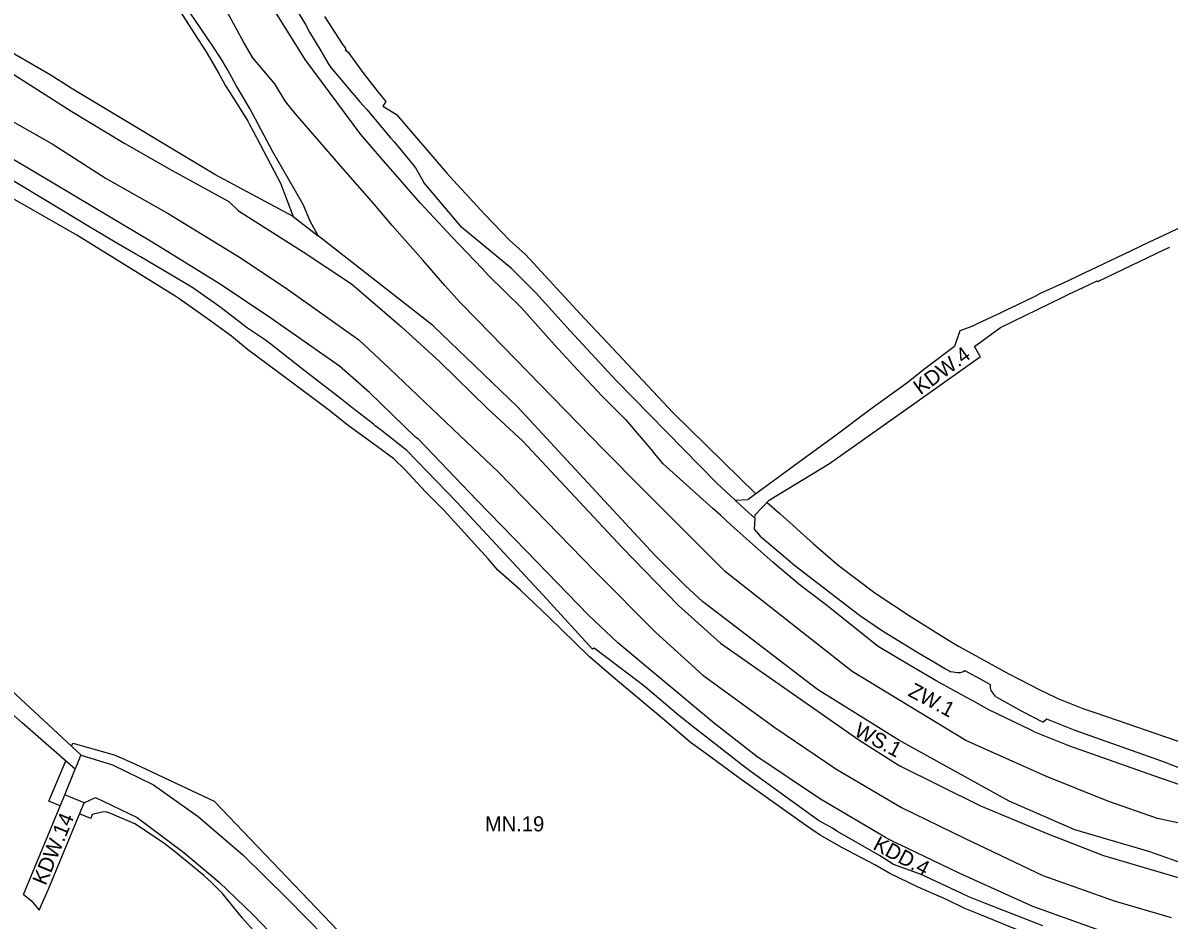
# Model space of a CAD drawing. Extents: x 7418991 to 7423142, y 5547704 to 5549547.
# Drawn here: x 7419654.4 to 7420035, y 5548518.9 to 5548816.8 of the extents above; entities that cross this region are included whole.
import ezdxf

# ---------------------------------------------------------------- set-up
doc = ezdxf.new("R2010")
doc.units = 0
for name, color, linetype in [('LIN_Linia Zabudowy Nieprzekraczalna', 7, 'Continuous'), ('LIN_linie_rozgraniczajace', 7, 'Continuous'), ('TXT_Oznaczenia_przeznaczen', 7, 'Continuous')]:
    doc.layers.add(name, color=color, linetype=linetype)

msp = doc.modelspace()

# ---------------------------------------------------------------- linework, layer by layer
at = {"layer": 'LIN_Linia Zabudowy Nieprzekraczalna'}
for p, q in [((7419937.32, 5548627.58), (7419949.3, 5548619.59)), ((7419691.76, 5548570.62), (7419717.86, 5548558.33)), ((7419666.76, 5548556.84), (7419663.06, 5548558.36)), ((7419717.86, 5548558.33), (7419819.96, 5548451.81))]:
    msp.add_line(p, q, dxfattribs=at)
for points in [[(7419754.53, 5548818.94), (7419759.18, 5548811.75), (7419760.41, 5548809.86), (7419761.61, 5548808.2), (7419761.39, 5548807.85), (7419762.33, 5548807.21), (7419767.57, 5548799.96), (7419772.34, 5548793.88), (7419774.86, 5548790.72), (7419773.92, 5548789.24), (7419778.4, 5548786.37), (7419795.11, 5548766.94), (7419796.13, 5548765.86), (7419806.44, 5548754.65), (7419807.78, 5548753.26), (7419816.01, 5548744.72), (7419821.27, 5548739.89), (7419840.89, 5548718.65), (7419846.84, 5548712.32), (7419870.33, 5548687.32), (7419897.75, 5548660.43)], [(7419986.71, 5548514.81), (7419972.13, 5548520.75), (7419967.13, 5548522.75), (7419961.25, 5548525.56), (7419951.7, 5548529.86), (7419942.26, 5548534.33), (7419937.31, 5548537.26), (7419926.3, 5548542.97), (7419919.08, 5548547.12), (7419914.29, 5548550.42), (7419892.49, 5548565.85), (7419881.13, 5548574.18), (7419876.11, 5548577.89), (7419868.06, 5548584.71), (7419868.09, 5548584.68), (7419851.11, 5548598.84), (7419842.52, 5548606.35), (7419837.65, 5548611.12), (7419829.01, 5548619.47), (7419819.47, 5548628.55), (7419812.05, 5548635.09), (7419808.83, 5548638.85), (7419794.23, 5548654.87), (7419788.11, 5548661.14), (7419783.95, 5548665.51), (7419781.38, 5548668.37), (7419777.69, 5548671.99), (7419777.58, 5548672.08), (7419772.17, 5548676.08), (7419766.82, 5548679.97), (7419762.37, 5548683.12), (7419757.56, 5548686.96), (7419756.3, 5548687.99), (7419751.87, 5548691.33), (7419739.32, 5548700.74), (7419729.02, 5548708.43), (7419723.61, 5548712.8), (7419715.97, 5548718.38), (7419706.15, 5548725.28), (7419705.21, 5548726.01), (7419672.29, 5548746.33), (7419651.66, 5548758.24)], [(7419901.48, 5548657.59), (7419905.76, 5548653.92), (7419916.9, 5548643.82), (7419925.15, 5548636.77), (7419937.32, 5548627.58)], [(7419949.3, 5548619.59), (7419956.38, 5548615.21), (7419961.76, 5548611.89), (7419965.11, 5548609.9), (7419981.5, 5548600.8)], [(7419981.5, 5548600.8), (7419992.1, 5548595.34), (7419997.1, 5548592.94), (7419998.04, 5548592.5), (7420006.38, 5548589.15), (7420010.64, 5548587.74), (7420040.89, 5548577.34), (7420048.53, 5548574.46), (7420054.4, 5548572.62), (7420067.89, 5548569.27), (7420082.96, 5548566.23), (7420086.13, 5548563.32), (7420087.87, 5548565.39), (7420099.95, 5548563.83)], [(7419670.56, 5548576.59), (7419670.98, 5548577.59)], [(7419670.98, 5548577.59), (7419684.69, 5548573.79), (7419686.98, 5548572.8), (7419691.76, 5548570.62)], [(7419663.06, 5548558.36), (7419668.6, 5548571.82)], [(7419744.03, 5548500.72), (7419727.35, 5548519.57), (7419720.7, 5548527.73), (7419717.06, 5548531.35), (7419714.5, 5548533.71), (7419708.88, 5548538.35), (7419704.11, 5548542.21), (7419700.7, 5548544.76), (7419691.58, 5548550.83), (7419683.24, 5548554.35), (7419682.25, 5548554.73), (7419681.66, 5548554.86), (7419680.74, 5548554.67), (7419677.44, 5548553.91), (7419676.93, 5548552.65), (7419673.23, 5548554.17)]]:
    msp.add_lwpolyline(points, dxfattribs=at)
at = {"layer": 'LIN_linie_rozgraniczajace'}
for p, q in [((7419727.78, 5548810.3), (7419722.21, 5548820.53)), ((7419730.71, 5548805.22), (7419727.78, 5548810.3)), ((7419738.01, 5548796.65), (7419730.71, 5548805.22)), ((7419629.93, 5548795.98), (7419664.13, 5548776.68)), ((7419741.56, 5548790.77), (7419738.01, 5548796.65)), ((7419744.88, 5548786.66), (7419741.56, 5548790.77)), ((7419760.78, 5548768.35), (7419744.88, 5548786.66)), ((7419664.13, 5548776.68), (7419682.01, 5548765.19)), ((7419770.98, 5548756.66), (7419760.78, 5548768.35)), ((7419784.81, 5548768.75), (7419787.49, 5548763.79)), ((7419682.01, 5548765.19), (7419702.58, 5548753.57)), ((7419777.06, 5548749.55), (7419770.98, 5548756.66)), ((7419702.58, 5548753.57), (7419726.89, 5548738.7)), ((7419744.14, 5548752.54), (7419752.39, 5548746.16)), ((7419787.26, 5548737.92), (7419777.06, 5548749.55)), ((7419726.89, 5548738.7), (7419742.2, 5548728.4)), ((7419794.52, 5548729.6), (7419787.26, 5548737.92)), ((7419824.87, 5548727.13), (7419816.59, 5548735.31)), ((7419819.8, 5548722.3), (7419809.09, 5548732.89)), ((7419742.2, 5548728.4), (7419765.96, 5548711.61)), ((7419799.48, 5548724.12), (7419794.52, 5548729.6)), ((7419805.23, 5548718.21), (7419799.48, 5548724.12)), ((7419734.93, 5548711.49), (7419728.96, 5548715.51)), ((7419847.2, 5548675.17), (7419805.23, 5548718.21)), ((7419765.96, 5548711.61), (7419776.19, 5548701.96)), ((7419776.19, 5548701.96), (7419799.52, 5548679.82)), ((7419884.76, 5548664.03), (7419851.55, 5548698)), ((7419854.5, 5548685.15), (7419863.51, 5548674.45)), ((7419799.52, 5548679.82), (7419812.24, 5548667.78)), ((7419860.22, 5548661.95), (7419847.2, 5548675.17)), ((7419812.24, 5548667.78), (7419844.34, 5548634.78)), ((7419869.72, 5548652.42), (7419860.22, 5548661.95)), ((7419890.92, 5548658.32), (7419895.25, 5548658.6)), ((7419877.85, 5548644.36), (7419869.72, 5548652.42)), ((7419897.47, 5548652.39), (7419897.54, 5548653.52)), ((7419887.7, 5548634.51), (7419877.85, 5548644.36)), ((7419844.34, 5548634.78), (7419864.56, 5548614.41)), ((7419929.74, 5548601.42), (7419887.7, 5548634.51)), ((7419851.92, 5548610.94), (7419842.08, 5548620.22)), ((7419864.56, 5548614.41), (7419880.15, 5548600.19)), ((7419884.02, 5548584.12), (7419851.92, 5548610.94)), ((7419967.48, 5548578.48), (7419929.74, 5548601.42)), ((7419880.15, 5548600.19), (7419904.1, 5548582.84)), ((7419994.36, 5548585.58), (7419993.22, 5548584.61)), ((7419904.1, 5548582.84), (7419924.32, 5548569.12)), ((7419994.3, 5548566.54), (7419967.48, 5548578.48)), ((7419924.32, 5548569.12), (7419946.14, 5548556.24)), ((7420014.64, 5548558.32), (7419994.3, 5548566.54)), ((7419674.75, 5548557.87), (7419668.28, 5548560.53)), ((7419946.14, 5548556.24), (7419967.03, 5548546.06)), ((7420031.14, 5548552.63), (7420014.64, 5548558.32)), ((7420048.85, 5548548.76), (7420031.14, 5548552.63)), ((7419940.8, 5548546.35), (7419945.27, 5548544.1)), ((7419967.03, 5548546.06), (7419993.09, 5548533.7)), ((7419993.09, 5548533.7), (7420016.69, 5548525.28)), ((7420016.69, 5548525.28), (7420035.64, 5548519.71))]:
    msp.add_line(p, q, dxfattribs=at)
for points in [[(7419725.26, 5548796.05), (7419722.48, 5548801.11), (7419720.88, 5548803.83), (7419720.03, 5548805.19), (7419717.65, 5548808.74), (7419713.44, 5548815.02), (7419708.31, 5548822.59), (7419706.01, 5548826.24), (7419702.41, 5548832.08), (7419698.25, 5548838.79), (7419694.79, 5548844.36), (7419690.11, 5548854.93), (7419687.2, 5548861.42), (7419682.37, 5548869.22), (7419679.61, 5548873.71), (7419676.54, 5548879.52), (7419674.86, 5548882.62)], [(7419717.15, 5548869.39), (7419723.59, 5548857.61), (7419729.07, 5548847.98), (7419748.22, 5548816.34), (7419749.51, 5548813.77), (7419753.32, 5548807.54), (7419755.8, 5548803.39), (7419756.6, 5548802), (7419763.76, 5548793.63), (7419766.31, 5548790.65), (7419768.6, 5548788.05), (7419776.43, 5548778.71), (7419777.63, 5548777.29), (7419780.05, 5548774.53), (7419784.81, 5548768.75)], [(7419681.66, 5548865.01), (7419686.39, 5548855.19), (7419695.39, 5548836.11), (7419700.86, 5548829.76), (7419707.66, 5548819.11), (7419711.37, 5548813.25), (7419715.25, 5548807.22), (7419719.45, 5548799.99), (7419721.69, 5548795.94)], [(7419773.52, 5548771.86), (7419766.66, 5548779.77), (7419748.11, 5548804.68), (7419735.05, 5548825.68), (7419723.7, 5548844.72)], [(7419672.39, 5548793.99), (7419670.45, 5548795.12), (7419663.47, 5548799.57), (7419645.7, 5548809.82), (7419626.86, 5548821.22), (7419612.15, 5548830.31), (7419604.5, 5548834.35), (7419599.55, 5548837.33), (7419592.42, 5548841.53), (7419590.61, 5548842.54)], [(7419625.5, 5548814.25), (7419646.9, 5548802.53), (7419670.62, 5548787.47), (7419688.23, 5548776.78), (7419703.95, 5548767.79), (7419722.74, 5548757.55), (7419726.03, 5548754.45), (7419747.43, 5548740.85), (7419763.5, 5548730.15), (7419780.13, 5548715.88), (7419792.86, 5548704.27), (7419808.71, 5548688.73), (7419820.43, 5548677.88), (7419853.39, 5548642.59), (7419872.11, 5548623.4), (7419886.03, 5548610.8), (7419931.98, 5548578.77), (7419945.38, 5548570.24), (7419972.32, 5548556.78), (7419994.74, 5548547.57), (7420013.19, 5548540.38), (7420039.08, 5548532.71)], [(7419721.69, 5548795.94), (7419723.07, 5548793.77), (7419724.4, 5548791.65), (7419725.74, 5548789.54), (7419727.08, 5548787.4), (7419728.41, 5548785.29), (7419729.11, 5548784.19), (7419729.67, 5548783.13), (7419730.85, 5548780.92), (7419735.5, 5548772.05), (7419739.88, 5548763.61), (7419744.14, 5548752.54), (7419718.18, 5548766.44), (7419672.39, 5548793.99)], [(7419880.08, 5548624.72), (7419874.36, 5548629.84), (7419864.28, 5548640.06), (7419837.73, 5548668.58), (7419818.59, 5548689.36), (7419790.53, 5548716.39), (7419752.39, 5548746.16), (7419749.83, 5548751.02), (7419747.43, 5548756.52), (7419742.36, 5548765.35), (7419737.4, 5548774.06), (7419729.71, 5548788.36), (7419725.26, 5548796.05)], [(7419784.8, 5548679.24), (7419769.44, 5548694.15), (7419759.49, 5548702.88), (7419736.73, 5548718.74), (7419720.21, 5548729.84), (7419697.28, 5548744.04), (7419677.6, 5548755.76), (7419657.58, 5548767.66), (7419640.53, 5548777.71)], [(7419809.09, 5548732.89), (7419806.87, 5548735.33), (7419796.98, 5548745.67), (7419786.34, 5548757.03), (7419783.16, 5548760.68), (7419780.37, 5548763.94), (7419773.52, 5548771.86)], [(7419728.96, 5548715.51), (7419720.27, 5548722.23), (7419717.94, 5548723.83), (7419710.46, 5548729.13), (7419693.47, 5548739.11), (7419691.92, 5548740.02), (7419685.6, 5548743.73), (7419677.45, 5548748.53), (7419666.76, 5548755), (7419647.49, 5548766.65)], [(7419816.59, 5548735.31), (7419800.13, 5548748.9), (7419787.49, 5548763.79)], [(7420048.98, 5548753.84), (7420034.77, 5548747.05), (7420028.32, 5548744.02), (7420022.17, 5548741.05), (7420006.82, 5548733.72), (7419999.56, 5548730.35), (7419992.15, 5548726.93), (7419990.41, 5548726), (7419984.39, 5548723.1), (7419981.06, 5548721.51), (7419978.65, 5548720.29), (7419971.69, 5548717.07), (7419969.52, 5548716.05), (7419965.54, 5548714.54), (7419963.78, 5548709.33), (7419953.83, 5548701.96), (7419947.9, 5548697.2), (7419935.64, 5548688.32), (7419924.39, 5548679.89), (7419911.81, 5548670.7), (7419895.25, 5548658.6)], [(7419972.12, 5548706.25), (7419970.32, 5548709.33), (7419979.01, 5548715.71), (7419999.49, 5548725.68), (7420000.55, 5548726.2), (7420001.72, 5548726.73), (7420006.42, 5548728.93), (7420011.14, 5548731.21), (7420011.28, 5548730.99), (7420033.45, 5548741.57), (7420035.26, 5548742.34)], [(7419824.87, 5548727.13), (7419836.08, 5548714.63), (7419851.55, 5548698)], [(7419854.5, 5548685.15), (7419850.5, 5548689.15), (7419846.51, 5548693.14), (7419838.71, 5548701.53), (7419830.91, 5548709.91), (7419825.36, 5548716.11), (7419819.8, 5548722.3)], [(7419773.31, 5548681.54), (7419771.35, 5548683.08), (7419770.76, 5548683.54), (7419763.62, 5548689.11), (7419760.25, 5548691.74), (7419746.73, 5548702.28), (7419736.26, 5548710.45), (7419734.99, 5548711.44), (7419734.93, 5548711.49)], [(7419897.54, 5548653.52), (7419902.23, 5548658.37), (7419922.24, 5548670.57), (7419952.05, 5548691.67), (7419972.38, 5548706.06), (7419972.12, 5548706.25)], [(7419993.01, 5548516.98), (7419973.97, 5548524.43), (7419968.48, 5548526.58), (7419964.31, 5548528.55), (7419952.61, 5548534.02), (7419943.42, 5548537.3), (7419938.84, 5548540.31), (7419924.63, 5548548.43), (7419923.24, 5548549.37), (7419918.61, 5548551.97), (7419896.18, 5548568.1), (7419893.14, 5548570.45), (7419880.41, 5548580.46), (7419879.08, 5548581.38), (7419872.17, 5548586.87), (7419861.12, 5548596.21), (7419858.64, 5548598.11), (7419844.11, 5548609.24), (7419843.57, 5548608.87), (7419828.36, 5548625.41), (7419814.25, 5548640.75), (7419798.45, 5548657.68), (7419781.89, 5548674.84), (7419773.42, 5548681.46), (7419773.31, 5548681.54)], [(7419805.17, 5548658.39), (7419785.7, 5548678.56), (7419784.8, 5548679.24)], [(7419886.01, 5548653.33), (7419883.44, 5548655.57), (7419866.96, 5548670.35), (7419863.51, 5548674.45)], [(7419884.76, 5548664.03), (7419890.77, 5548658.46)], [(7419842.08, 5548620.22), (7419821.56, 5548641.41), (7419805.17, 5548658.39)], [(7419890.77, 5548658.46), (7419890.92, 5548658.32), (7419894.25, 5548655.24), (7419897.47, 5548652.39)], [(7419938.41, 5548609.69), (7419920.74, 5548623.75), (7419912.62, 5548629.97), (7419903.52, 5548637.69), (7419889.55, 5548650.05), (7419886.01, 5548653.33)], [(7419897.47, 5548652.39), (7419897.26, 5548648.76), (7419899.24, 5548646.34), (7419906.17, 5548640.55), (7419910.72, 5548636.59), (7419932.16, 5548620.15), (7419939.46, 5548615.19), (7419944.68, 5548611.94), (7419952.14, 5548607.37), (7419956.84, 5548604.6), (7419960.72, 5548602.27), (7419962.49, 5548601.29)], [(7419671.78, 5548569.04), (7419654.18, 5548584.43), (7419634.31, 5548601.81), (7419626.95, 5548608.32), (7419622.06, 5548612.67), (7419617.81, 5548616.49), (7419613.48, 5548620.31), (7419613.36, 5548620.41), (7419601.41, 5548629.83), (7419597.43, 5548632.85), (7419593.79, 5548635.76)], [(7419673.74, 5548573.64), (7419634.95, 5548609.61), (7419631.03, 5548613.4), (7419630.33, 5548613.28), (7419627.38, 5548616.03), (7419620.71, 5548621.63), (7419610.91, 5548629.87), (7419600.03, 5548637.69)], [(7420073.76, 5548529.37), (7420047.08, 5548535), (7420028.23, 5548541.62), (7420003.67, 5548548.84), (7419981.84, 5548558.41), (7419945.29, 5548578.67), (7419918.24, 5548595.43), (7419880.08, 5548624.72)], [(7419990.07, 5548581.55), (7419989.15, 5548581.99), (7419975.14, 5548588.7), (7419970.03, 5548591.55), (7419969.1, 5548592.07), (7419957.85, 5548598.26), (7419948.83, 5548603.51), (7419938.41, 5548609.69)], [(7419977.39, 5548593.09), (7419976.59, 5548594.23), (7419975.89, 5548595.12), (7419975.65, 5548596.01), (7419975.73, 5548596.99), (7419974.1, 5548597.88), (7419972.41, 5548598.87), (7419968.07, 5548601.23), (7419967.2, 5548601.63), (7419966.56, 5548601.32), (7419965.61, 5548601.05), (7419964.71, 5548600.94), (7419962.49, 5548601.29)], [(7419977.39, 5548593.09), (7419986.11, 5548588.29), (7419993.22, 5548584.61)], [(7420034.67, 5548570.9), (7420031.56, 5548571.99), (7420003.77, 5548581.81), (7419994.36, 5548585.58)], [(7419940.8, 5548546.35), (7419919.27, 5548559.05), (7419898.09, 5548573.18), (7419884.02, 5548584.12)], [(7419990.07, 5548581.55), (7419990.27, 5548581.45), (7420001.88, 5548576.8), (7420029.78, 5548566.94), (7420041.31, 5548562.9), (7420059.95, 5548557.78), (7420063.71, 5548556.99), (7420075.61, 5548554.14)], [(7419672.04, 5548569.67), (7419673.57, 5548573.37), (7419673.74, 5548573.64), (7419684.13, 5548570.46)], [(7419684.13, 5548570.46), (7419697.75, 5548563.75), (7419712.63, 5548553.29), (7419727.44, 5548540.59), (7419742.18, 5548526.09), (7419754.71, 5548513.21)], [(7420034.67, 5548570.9), (7420045.99, 5548566.58), (7420047.18, 5548566.19), (7420047.54, 5548565.04), (7420053.19, 5548563.48), (7420061.12, 5548561.38), (7420063.33, 5548560.8), (7420067.38, 5548559.83), (7420076.27, 5548557.69), (7420079, 5548557.36), (7420083.76, 5548556.71), (7420099.84, 5548554.53)], [(7419654.63, 5548527.38), (7419668.28, 5548560.53), (7419671.78, 5548569.04), (7419672.04, 5548569.67)], [(7419674.75, 5548557.87), (7419678.47, 5548559.55), (7419692.3, 5548552.97), (7419707.79, 5548541.3), (7419719.52, 5548531.53), (7419730.82, 5548520.64), (7419749.71, 5548501.07)], [(7419659.83, 5548522.21), (7419660.98, 5548524.98), (7419662.83, 5548528.92), (7419674.75, 5548557.87)], [(7420032.55, 5548508.76), (7420013.86, 5548514.78), (7419989.73, 5548523.36), (7419965.32, 5548534.48), (7419945.27, 5548544.1)], [(7419654.63, 5548527.38), (7419657.13, 5548525.34), (7419659.83, 5548522.21)]]:
    msp.add_lwpolyline(points, dxfattribs=at)

# ---------------------------------------------------------------- texts
at = {"layer": 'TXT_Oznaczenia_przeznaczen'}
for s, rotation, p in [('KDW.4', 36.283, (7419952.42, 5548693.13)), ('ZW.1', 332.1212, (7419947.99, 5548593.5)), ('WS.1', 332.2128, (7419930.04, 5548580.35)), ('KDW.14', 67.4229, (7419661.96, 5548530.12)), ('KDD.4', 332.2263, (7419936.3, 5548542.56))]:
    msp.add_text(s, height=5, rotation=rotation, dxfattribs=at).set_placement(p)
msp.add_text('MN.19', height=5, dxfattribs=at).set_placement((7419807.82, 5548548.34))

doc.saveas('drawing.dxf')
